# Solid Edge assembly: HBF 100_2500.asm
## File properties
Title: Zylinder
Author: bmolnar
Template: iso assembly.asm
Last saved by: bmolnar
Revision: 66
Application: Solid Edge
Username: bmolnar
Dokumentum tartalom típus: 1
Document Number: HBF 100/2500
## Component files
Kit.par
Profilrohr.par
Kolbenstange_1.par
Mutter.par
Kolbenstange_2.par
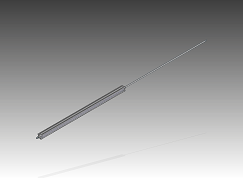
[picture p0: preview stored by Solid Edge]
